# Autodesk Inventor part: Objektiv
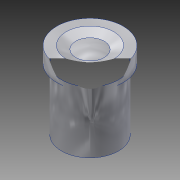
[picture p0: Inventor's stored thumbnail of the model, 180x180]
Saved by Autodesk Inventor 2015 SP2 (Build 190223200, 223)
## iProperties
Created: 2012-10
Part Number: Objektiv
Material: Aluminium 6061
Document SubType Name: Modeling
Designer: rYan
Density: 2.71 g/cm^3
Mass: 5.24813 g
Surface Area: 9.57222 cm^2
Volume: 1.93658 cm^3
Appearance: Aluminium - flach
Author: rYan
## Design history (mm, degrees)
sketch "Skizze5"
  geometry: L1 (-8.47, 0)-(1.821, 0) reference; L2 (-3, 0)-(-6, 0); L3 (-6, 0)-(-6, 13); L4 (-6, 13)-(-7, 13); L5 (-7, 13)-(-7, 16.3); L6 (-7, 16.3)-(-5, 16.3); L7 (-5, 16.3)-(-3, 15.572); L8 (-3, 0)-(-3, 0.5); L9 (-3, 0.5)-(0, 0.5); L10 (0, -3.289)-(0, 19.735) reference; L11 (0, 16.3)-(0, 0.5); A1 r 8 centre (0.351, 8.308) between (0, 16.3) and (-3, 15.572); 1 further point
  constraints: 18 end point, 3 parallel, 3 perpendicular, 2 point on circle, 2 point on line, 1 centre point, 1 collinear
  dimensions: "d12" = 6 distance of point (0, 0) L2.end; "d13" = 13 distance of L2.end L3.end; "d14" = 1 distance of L3.end L4.end; "d15" = 3.3 distance of L4.end L5.end; "d16" = 2 distance of L5.end L6.end; "d17" = 160 deg angle of L6 L7; "d18" = 2 horizontal distance of L7.end L6.end; "d19" = 8 radius of A1; "d23" = 0.5 distance of L2.start L8.end; "d24" = 3 distance of L8.end L9.end
revolve "Umdrehung1" sketch "Skizze5" stored, may be unused: angle "d20" = 90 deg
node "Volumenkörper2"
